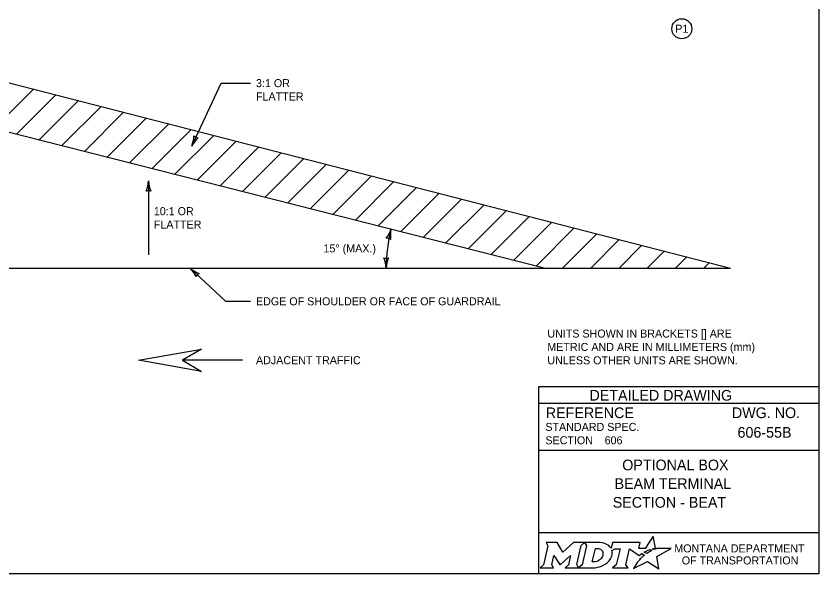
# Model space of a CAD drawing. Extents: x 49991.4 to 50021, y 49987.6 to 50011.4.
# Drawn here: x 50010.73 to 50016.75, y 49987.8 to 49991.98 of the extents above; entities that cross this region are included whole.
import ezdxf

# ---------------------------------------------------------------- set-up
doc = ezdxf.new("R2010")
doc.units = 0
for name, color, linetype in [('Default', 7, 'Continuous'), ('Level 1', 7, 'Continuous'), ('Level 2', 7, 'Continuous'), ('Level 3', 7, 'Continuous'), ('Level 5', 7, 'Continuous')]:
    doc.layers.add(name, color=color, linetype=linetype)

msp = doc.modelspace()

# ---------------------------------------------------------------- linework, layer by layer
at = {"layer": 'Default'}
for points in [[(50015.5126, 49987.9811), (50015.5023, 49987.9867), (50015.5139, 49987.9895), (50015.5255, 49987.9915), (50015.5081, 49988.0816), (50015.4486, 49987.9903), (50015.4013, 49987.9896), (50015.4116, 49988.0337), (50015.2024, 49988.0338), (50015.1923, 49987.9913), (50015.1865, 49987.9996)], [(50014.7056, 49988.0338), (50014.7197, 49988.0104), (50014.6862, 49987.8671), (50014.6605, 49987.8446), (50014.7621, 49987.8446), (50014.7486, 49987.8674), (50014.7648, 49987.9375), (50014.8085, 49987.8685), (50014.8138, 49987.8685), (50014.8889, 49987.938), (50014.8725, 49987.8669), (50014.8478, 49987.8449), (50014.9494, 49987.8449), (50014.9356, 49987.8682), (50014.9688, 49988.0106)], [(50014.9688, 49988.0106), (50014.9941, 49988.0338), (50014.9117, 49988.0338), (50014.8321, 49987.9608), (50014.7876, 49988.0335), (50014.7056, 49988.0338)], [(50015.1077, 49988.0338), (50014.9941, 49988.0338), (50015.0088, 49988.0109), (50014.9749, 49987.8671), (50014.9494, 49987.8449), (50015.06, 49987.8449)], [(50015.1317, 49987.9471), (50015.1305, 49987.939), (50015.1273, 49987.9297), (50015.1231, 49987.9215), (50015.1175, 49987.914), (50015.111, 49987.9071), (50015.1031, 49987.9008), (50015.0948, 49987.8961), (50015.0857, 49987.8922), (50015.0766, 49987.8899), (50015.0674, 49987.889), (50015.0515, 49987.889), (50015.0751, 49987.989), (50015.0911, 49987.989), (50015.0987, 49987.9884), (50015.1063, 49987.9865), (50015.1129, 49987.9835), (50015.119, 49987.9793), (50015.1238, 49987.9743), (50015.1275, 49987.9683), (50015.1302, 49987.9621), (50015.1318, 49987.9547), (50015.1318, 49987.9517), (50015.1317, 49987.9471)], [(50015.1991, 49987.9747), (50015.2237, 49987.9878), (50015.2606, 49987.9878), (50015.232, 49987.8673), (50015.2045, 49987.8446), (50015.3207, 49987.8446), (50015.3037, 49987.8675), (50015.3319, 49987.9877), (50015.4032, 49987.936), (50015.4243, 49987.9511), (50015.444, 49987.9402)], [(50015.3882, 49987.8843), (50015.3729, 49987.8599), (50015.3682, 49987.8524), (50015.3624, 49987.8438), (50015.3601, 49987.8395), (50015.4654, 49987.8926), (50015.5493, 49987.8375), (50015.5362, 49987.9302), (50015.6431, 49987.9886), (50015.5938, 49987.9894), (50015.5637, 49987.9898), (50015.5429, 49987.9901), (50015.5361, 49987.9886), (50015.5312, 49987.9874), (50015.5228, 49987.9851), (50015.5126, 49987.9811)], [(50015.4622, 49987.9535), (50015.4598, 49987.9518), (50015.4415, 49987.9614), (50015.4518, 49987.9671), (50015.4559, 49987.9693), (50015.4645, 49987.9733), (50015.4702, 49987.9759), (50015.4781, 49987.9789), (50015.4854, 49987.9816), (50015.4972, 49987.9742), (50015.4932, 49987.9721), (50015.4886, 49987.9696), (50015.4844, 49987.9674), (50015.4794, 49987.9645), (50015.4775, 49987.9634), (50015.4748, 49987.9618), (50015.4723, 49987.9604), (50015.47, 49987.9588), (50015.4674, 49987.957), (50015.4647, 49987.9552), (50015.4622, 49987.9535)], [(50015.4021, 49987.9004), (50015.4021, 49987.9004)], [(50015.1057, 49987.8522), (50015.1141, 49987.8548), (50015.1271, 49987.8602), (50015.1475, 49987.8712)]]:
    msp.add_lwpolyline(points, dxfattribs=at)
for centre, radius, start, end in [((50015.1308, 49987.9554), 0.0709, 339.53292, 15.85821), ((50015.0868, 49987.9727), 0.1183, 300.91025, 339.13831)]:
    msp.add_arc(centre, radius, start, end, dxfattribs=at)
for centre, major_axis, ratio, start_param, end_param in [((50015.1056, 49987.9864), (0.0834, -0.0037), 0.568097, 0.61298, 1.570796), ((50015.1612, 49987.9937), (0.0361, -0.0295), 0.469099, 1.225588, 1.570796), ((50015.4329, 49987.9305), (-0.0112, -0.0097), 0.021651, 3.157348, 6.283185), ((50015.3952, 49987.8923), (-0.00694, -0.00806), 0.008222, 0, 3.137361), ((50015.4119, 49987.9106), (-0.0098, -0.0102), 0.016458, 3.141593, 6.279097), ((50015.0603, 49987.9932), (0, 0.1484), 0.987302, 3.139398, 3.456847)]:
    msp.add_ellipse(centre, major_axis=major_axis, ratio=ratio, start_param=start_param, end_param=end_param, dxfattribs=at)
at = {"layer": 'Level 1'}
for p, q in [((50010.3087, 49991.5719), (50016.0878, 49990.0886)), ((50010.5708, 49991.1348), (50010.8651, 49991.4291)), ((50010.7391, 49991.0911), (50011.0338, 49991.3858)), ((50010.9085, 49991.0483), (50011.2027, 49991.3424)), ((50011.0778, 49991.0054), (50011.3715, 49991.2991)), ((50011.247, 49990.9626), (50011.5402, 49991.2558)), ((50010.3072, 49991.2004), (50014.7014, 49990.0886)), ((50011.4164, 49990.9198), (50011.7091, 49991.2124)), ((50011.5857, 49990.8769), (50011.878, 49991.1691)), ((50011.7549, 49990.8341), (50012.0467, 49991.1258)), ((50011.9243, 49990.7912), (50012.2155, 49991.0825)), ((50012.0936, 49990.7484), (50012.3844, 49991.0391)), ((50012.2628, 49990.7056), (50012.5531, 49990.9958)), ((50012.4321, 49990.6627), (50012.7219, 49990.9525)), ((50012.6015, 49990.6199), (50012.8908, 49990.9091)), ((50012.7707, 49990.5771), (50013.0595, 49990.8658)), ((50012.9401, 49990.5342), (50013.2284, 49990.8225)), ((50013.1093, 49990.4914), (50013.3971, 49990.7792)), ((50013.2786, 49990.4486), (50013.5659, 49990.7359)), ((50013.4479, 49990.4057), (50013.7348, 49990.6925)), ((50013.6171, 49990.3629), (50013.9035, 49990.6492)), ((50013.7865, 49990.3201), (50014.0723, 49990.6059)), ((50013.9558, 49990.2772), (50014.2412, 49990.5625)), ((50014.125, 49990.2344), (50014.4099, 49990.5192)), ((50014.2944, 49990.1916), (50014.5788, 49990.4759)), ((50014.4638, 49990.1487), (50014.7476, 49990.4326)), ((50014.633, 49990.1059), (50014.9163, 49990.3893)), ((50014.8279, 49990.0886), (50015.0852, 49990.3459)), ((50015.04, 49990.0886), (50015.254, 49990.3026)), ((50015.2521, 49990.0886), (50015.4227, 49990.2593)), ((50015.4643, 49990.0886), (50015.5916, 49990.2159)), ((50015.6765, 49990.0886), (50015.7605, 49990.1726)), ((50015.8885, 49990.0886), (50015.9292, 49990.1293)), ((50012.4322, 49989.3992), (50011.9803, 49989.3992)), ((50012.4322, 49989.3987), (50011.9803, 49989.3987))]:
    msp.add_line(p, q, dxfattribs=at)
for points in [[(49999.3835, 49998.9992), (50016.7501, 49998.9992), (50016.7501, 49987.7988), (49999.3835, 49987.7988)], [(50012.1248, 49989.3154), (50011.6519, 49989.3987), (50012.1248, 49989.4825), (50011.9805, 49989.3987)]]:
    msp.add_lwpolyline(points, close=True, dxfattribs=at)
msp.add_lwpolyline([(50010.308, 49990.0886), (50016.0878, 49990.0886)], dxfattribs=at)
at = {"layer": 'Level 2'}
msp.add_circle((50015.7229, 49991.8806), 0.075, dxfattribs=at)
at = {"layer": 'Level 3'}
for p, q in [((50012.0507, 49991.0022), (50012.2715, 49991.4734)), ((50012.2715, 49991.4734), (50012.4922, 49991.4734)), ((50011.7268, 49990.7412), (50011.7268, 49990.1886)), ((50012.0389, 49990.0886), (50012.3044, 49989.84)), ((50012.3044, 49989.84), (50012.4922, 49989.84))]:
    msp.add_line(p, q, dxfattribs=at)
for centre, radius, start, end in [((50011.8351, 49991.0905), 0.233, 337.71995, 356.9698), ((50012.248, 49990.8996), 0.2223, 132.34865, 152.53216), ((50012.1051, 49991.1183), 0.0548, 227.03146, 262.75382), ((50011.5047, 49990.7504), 0.2223, 337.45601, 357.63952), ((50011.9595, 49990.7527), 0.233, 182.82731, 202.07716), ((50011.7268, 49990.613), 0.0548, 72.13882, 107.86118), ((50014.7014, 49990.0886), 1.1938, 165.80148, 179.99905), ((50013.3319, 49990.4477), 0.2223, 322.4581, 342.64161), ((50013.7718, 49990.3323), 0.233, 167.8294, 187.07925), ((50013.5109, 49990.2576), 0.0548, 57.14091, 92.86327), ((50013.5076, 49990.2168), 0.0548, 252.13882, 287.86118), ((50013.2749, 49990.0771), 0.233, 2.82731, 22.07716), ((50013.7297, 49990.0794), 0.2223, 157.45601, 177.63952), ((50011.8804, 49989.9327), 0.2223, 24.33882, 44.52233), ((50012.1896, 49990.2663), 0.233, 229.71012, 248.95997), ((50012.1325, 49990.001), 0.0548, 119.02163, 154.74399)]:
    msp.add_arc(centre, radius, start, end, dxfattribs=at)
at = {"layer": 'Level 5'}
for p, q in [((50016.7501, 49989.1988), (50014.6501, 49989.1988)), ((50014.6501, 49989.1988), (50014.6501, 49987.7988)), ((50016.7501, 49989.0738), (50014.6501, 49989.0738)), ((50016.3862, 49988.8587), (50016.3862, 49988.8587)), ((50015.1444, 49988.7993), (50015.1444, 49988.7993)), ((50016.7501, 49988.7238), (50014.6501, 49988.7238)), ((50015.7001, 49988.4747), (50015.7001, 49988.4747)), ((50016.7501, 49988.1057), (50014.6501, 49988.1057))]:
    msp.add_line(p, q, dxfattribs=at)

# ---------------------------------------------------------------- texts
at = {"layer": 'Default'}
for s, p in [('MONTANA DEPARTMENT', (50015.6663, 49987.96)), ('OF TRANSPORTATION', (50015.7225, 49987.87))]:
    msp.add_text(s, height=0.06, dxfattribs=at).set_placement(p)
at = {"layer": 'Level 2'}
for s, height, p in [('P1', 0.06, (50015.6737, 49991.8506)), ('3:1 OR', 0.06, (50012.5322, 49991.4434)), ('FLATTER', 0.06, (50012.5322, 49991.3434)), ('10:1 OR', 0.06, (50011.7668, 49990.4849)), ('FLATTER', 0.06, (50011.7668, 49990.3849)), ('15° (MAX.)', 0.06, (50013.0379, 49990.2061)), ('EDGE OF SHOULDER OR FACE OF GUARDRAIL', 0.06, (50012.5322, 49989.81)), ('UNITS SHOWN IN BRACKETS [] ARE ', 0.06, (50014.7151, 49989.5683)), ('METRIC AND ARE IN MILLIMETERS (mm) ', 0.06, (50014.7151, 49989.4683)), ('ADJACENT TRAFFIC', 0.06, (50012.5322, 49989.3689)), ('UNLESS OTHER UNITS ARE SHOWN.', 0.06, (50014.7151, 49989.3683)), ('606-55B', 0.08, (50016.1402, 49988.8187)), ('606', 0.06, (50015.1444, 49988.7693)), ('OPTIONAL BOX', 0.08, (50015.2762, 49988.5747)), ('BEAM TERMINAL', 0.08, (50015.2189, 49988.4347)), ('SECTION - BEAT', 0.08, (50015.2049, 49988.2947))]:
    msp.add_text(s, height=height, dxfattribs=at).set_placement(p)
at = {"layer": 'Level 5'}
for s, height, p in [('DETAILED DRAWING', 0.0799, (50015.0311, 49989.0963)), ('REFERENCE', 0.08, (50014.7037, 49988.9654)), ('DWG. NO.', 0.08, (50016.0979, 49988.9654)), ('STANDARD SPEC.', 0.06, (50014.7004, 49988.8694)), ('SECTION', 0.06, (50014.7004, 49988.7694))]:
    msp.add_text(s, height=height, dxfattribs=at).set_placement(p)

doc.saveas('drawing.dxf')
